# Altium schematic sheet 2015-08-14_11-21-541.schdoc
size 539 x 193 mm; SheetNumber: 1; SheetTotal: 1
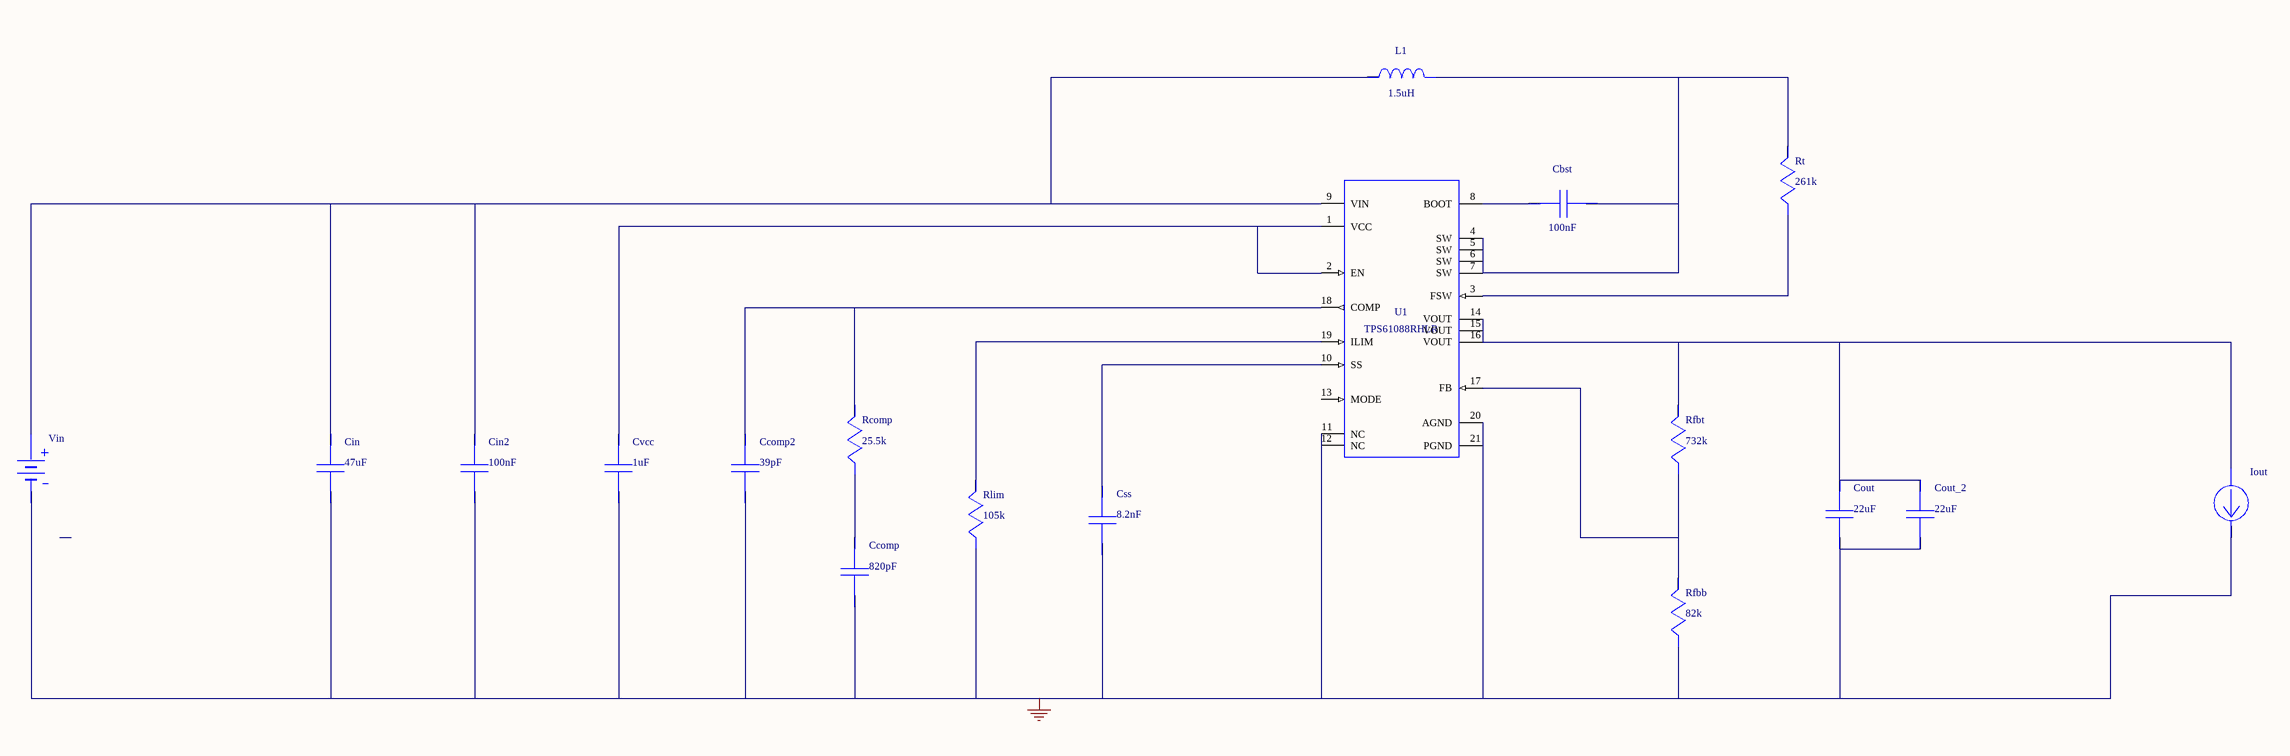
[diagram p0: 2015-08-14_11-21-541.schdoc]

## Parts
Cbst  value 100nF  (hidden comment: C1005X5R1A104K)
Ccomp  value 820pF  (hidden comment: CC0805KRX7R9BB821)
Ccomp2  value 39pF  (hidden comment: CC0805JRNPO9BN390)
Cin  value 47uF  (hidden comment: GRM32ER61C476ME15L)
Cin2  value 100nF  (hidden comment: GRM155R61C104KA88D)
Cout  value 22uF  (hidden comment: GRM32ER61E226KE15L)
Cout_2  value 22uF  (hidden comment: GRM32ER61E226KE15L)
Css  value 8.2nF  (hidden comment: GRM155R71C822KA01D)
Cvcc  value 1uF  (hidden comment: C1608X5R1A105K)
Iout  WB_CURRENT_LOAD  (value not drawn)
L1  value 1.5uH  (hidden comment: SRP6540-1R5M)
Rcomp  value 25.5k  (hidden comment: CRCW040225K5FKED)
Rfbb  value 82k  (hidden comment: RR1220P-823-D)
Rfbt  value 732k  (hidden comment: CRCW0402732KFKED)
Rlim  value 105k  (hidden comment: ERJ-8ENF1053V)
Rt  value 261k  (hidden comment: ERJ-8ENF2613V)
U1  TPS61088RHLR
Vin  WB_BATTERY  (value not drawn)

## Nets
0: Ccomp.2 Ccomp2.2 Cin.2 Cin2.2 Cout.2 Cout_2.2 Css.2 Cvcc.2 Iout.2(-) Rfbb.2 Rlim.2 U1.11(NC) U1.12(NC) U1.20(AGND) U1.21(PGND) Vin.2(-)
NetCbst_1: Cbst.1 U1.8(BOOT)
NetCbst_2: Cbst.2 L1.2 Rt.1 U1.4(SW) U1.5(SW) U1.6(SW) U1.7(SW)
NetCcomp2_1: Ccomp2.1 Rcomp.1 U1.18(COMP)
NetCcomp_1: Ccomp.1 Rcomp.2
NetCin_1: Cin.1 Cin2.1 L1.1 U1.9(VIN) Vin.1(+)
NetCout_1: Cout.1 Cout_2.1 Iout.1(+) Rfbt.1 U1.14(VOUT) U1.15(VOUT) U1.16(VOUT)
NetCss_1: Css.1 U1.10(SS)
NetCvcc_1: Cvcc.1 U1.1(VCC) U1.2(EN)
NetRfbb_1: Rfbb.1 Rfbt.2 U1.17(FB)
NetRlim_1: Rlim.1 U1.19(ILIM)
NetRt_2: Rt.2 U1.3(FSW)

Not connected (* = marked no-connect by the designer): U1 13(MODE)

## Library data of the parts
Cbst = C1005X5R1A104K: Manufacturer Name: TDK
Ccomp = CC0805KRX7R9BB821: CC0805KRX7R9BB82; Manufacturer Name: Yageo America
Ccomp2 = CC0805JRNPO9BN390: CC0805JRNPO9BN39; Manufacturer Name: Yageo America
Cin = GRM32ER61C476ME15L: GRM32ER61C476ME1; Manufacturer Name: MuRata
Cin2 = GRM155R61C104KA88D: GRM155R61C104KA8; Manufacturer Name: MuRata
Cout Cout_2 = GRM32ER61E226KE15L: GRM32ER61E226KE1; Manufacturer Name: MuRata
Css = GRM155R71C822KA01D: GRM155R71C822KA0; Manufacturer Name: MuRata
Cvcc = C1608X5R1A105K: Manufacturer Name: TDK
Iout = WB_CURRENT_LOAD: Value: UNLISTED
L1 = SRP6540-1R5M: Unknown; Manufacturer Name: Bourns
Rcomp = CRCW040225K5FKED: Manufacturer Name: Vishay-Dale
Rfbb = RR1220P-823-D: Manufacturer Name: Susumu Co Ltd
Rfbt = CRCW0402732KFKED: Manufacturer Name: Vishay-Dale
Rlim = ERJ-8ENF1053V: Manufacturer Name: Panasonic
Rt = ERJ-8ENF2613V: Manufacturer Name: Panasonic
U1 = TPS61088RHLR: Manufacturer Name: Texas Instruments; Value: UNLISTED
Vin = WB_BATTERY: Value: UNLISTED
